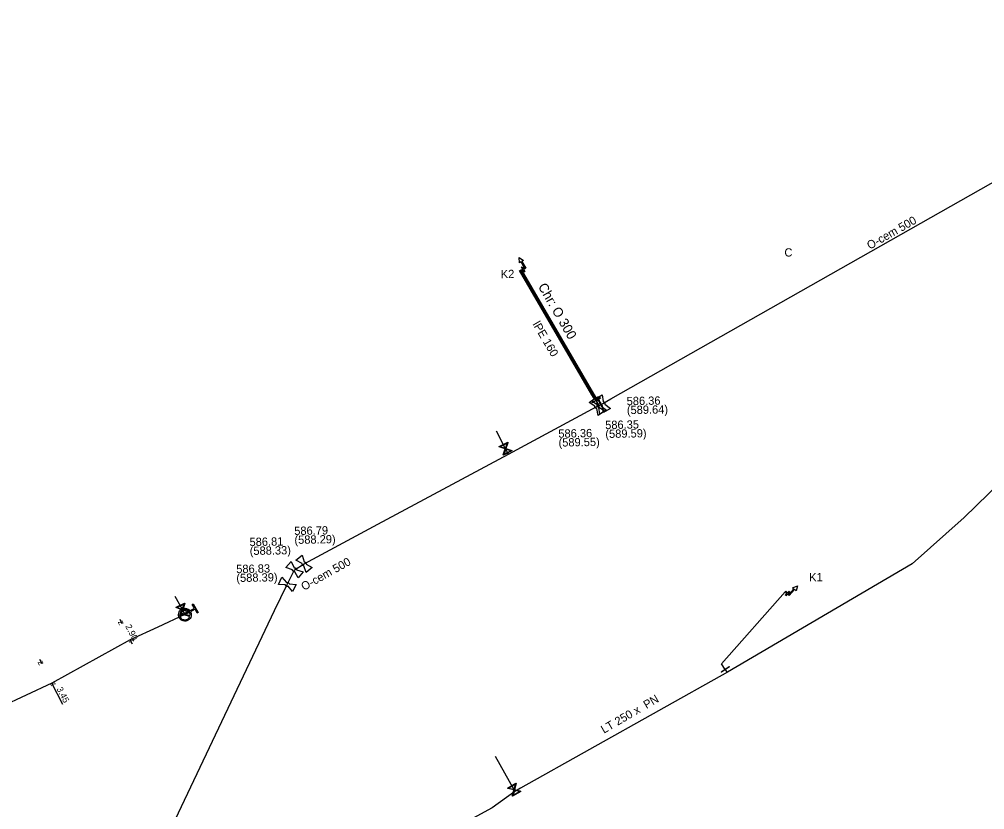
# Model space of a CAD drawing. Extents: x -643544 to -637295, y -1119190 to -1111715.
# Drawn here: x -641216.1 to -641064.3, y -1115318.9 to -1115194.6 of the extents above; entities that cross this region are included whole.
import ezdxf

# ---------------------------------------------------------------- set-up
doc = ezdxf.new("R2010")
doc.units = 0
for name, color, linetype in [('Default', 7, 'Continuous'), ('VP Chránička', 7, 'Continuous'), ('VP Chránička - okraje', 7, 'Continuous'), ('VP Hydrant', 7, 'Continuous'), ('VP Hydrant - popis', 7, 'Continuous'), ('VP Kótování', 7, 'Continuous'), ('VP Lomový bod', 7, 'Continuous'), ('VP Lomový bod - popis', 7, 'Continuous'), ('VP Popis nerozlišený', 7, 'Continuous'), ('VP Přípojka', 7, 'Continuous'), ('VP Řad', 7, 'Continuous'), ('VP Řad - označení', 7, 'Continuous'), ('VP Řad - popis', 7, 'Continuous'), ('VP Šoupě', 7, 'Continuous')]:
    doc.layers.add(name, color=color, linetype=linetype)

msp = doc.modelspace()

# ---------------------------------------------------------------- linework, layer by layer
at = {"layer": 'Default'}
for points in [[(-641125.25, -1115255.21), (-641125.2, -1115255.21), (-641125.15, -1115255.23), (-641125.07, -1115255.27), (-641125.03, -1115255.34), (-641124.98, -1115255.41), (-641124.97, -1115255.49), (-641124.96, -1115255.54), (-641124.98, -1115255.59)], [(-641124.98, -1115255.65), (-641125.03, -1115255.64), (-641125.08, -1115255.61), (-641125.15, -1115255.57), (-641125.2, -1115255.5), (-641125.24, -1115255.43), (-641125.24, -1115255.35), (-641125.24, -1115255.29), (-641125.23, -1115255.24)], [(-641124.88, -1115255.03), (-641124.83, -1115255.04), (-641124.78, -1115255.06), (-641124.71, -1115255.11), (-641124.66, -1115255.18), (-641124.62, -1115255.25), (-641124.62, -1115255.33), (-641124.62, -1115255.39), (-641124.63, -1115255.44)], [(-641124.39, -1115255.35), (-641124.45, -1115255.34), (-641124.49, -1115255.31), (-641124.57, -1115255.27), (-641124.61, -1115255.2), (-641124.65, -1115255.13), (-641124.65, -1115255.04), (-641124.65, -1115254.99), (-641124.64, -1115254.94)], [(-641124.29, -1115254.73), (-641124.23, -1115254.74), (-641124.19, -1115254.77), (-641124.11, -1115254.81), (-641124.07, -1115254.88), (-641124.03, -1115254.95), (-641124.03, -1115255.03), (-641124.03, -1115255.09), (-641124.04, -1115255.14)], [(-641125.31, -1115255.83), (-641125.36, -1115255.83), (-641125.41, -1115255.8), (-641125.49, -1115255.77), (-641125.53, -1115255.7), (-641125.58, -1115255.63), (-641125.59, -1115255.55), (-641125.6, -1115255.5), (-641125.58, -1115255.44)], [(-641172.87, -1115280.85), (-641172.82, -1115280.84), (-641172.77, -1115280.85), (-641172.68, -1115280.87), (-641172.62, -1115280.92), (-641172.56, -1115280.97), (-641172.53, -1115281.05), (-641172.51, -1115281.1), (-641172.51, -1115281.16)], [(-641171.33, -1115280.54), (-641171.38, -1115280.54), (-641171.43, -1115280.52), (-641171.51, -1115280.49), (-641171.56, -1115280.43), (-641171.61, -1115280.36), (-641171.63, -1115280.28), (-641171.64, -1115280.23), (-641171.63, -1115280.17)], [(-641171.31, -1115279.92), (-641171.26, -1115279.92), (-641171.21, -1115279.94), (-641171.13, -1115279.97), (-641171.08, -1115280.03), (-641171.03, -1115280.1), (-641171.01, -1115280.18), (-641171, -1115280.23), (-641171.01, -1115280.28)], [(-641172.77, -1115281.47), (-641172.82, -1115281.48), (-641172.88, -1115281.47), (-641172.96, -1115281.45), (-641173.02, -1115281.4), (-641173.08, -1115281.35), (-641173.11, -1115281.26), (-641173.13, -1115281.21), (-641173.13, -1115281.16)], [(-641173.84, -1115283.75), (-641173.89, -1115283.77), (-641173.94, -1115283.77), (-641174.03, -1115283.78), (-641174.1, -1115283.74), (-641174.17, -1115283.7), (-641174.22, -1115283.63), (-641174.25, -1115283.59), (-641174.26, -1115283.53)], [(-641174.08, -1115283.17), (-641174.03, -1115283.15), (-641173.98, -1115283.15), (-641173.89, -1115283.14), (-641173.82, -1115283.18), (-641173.75, -1115283.22), (-641173.7, -1115283.29), (-641173.67, -1115283.33), (-641173.66, -1115283.38)], [(-641189.16, -1115287.79), (-641189, -1115288.11), (-641189.09, -1115288.47), (-641189.19, -1115288.87), (-641189.55, -1115289.08), (-641189.91, -1115289.29), (-641190.31, -1115289.19), (-641190.71, -1115289.09), (-641190.92, -1115288.73), (-641191.13, -1115288.38), (-641191.03, -1115287.97), (-641190.93, -1115287.57), (-641190.57, -1115287.36), (-641190.22, -1115287.15), (-641189.82, -1115287.25), (-641189.46, -1115287.34), (-641189.25, -1115287.63)], [(-641190.87, -1115288.11), (-641190.9, -1115288.38), (-641190.76, -1115288.63), (-641190.59, -1115288.92), (-641190.26, -1115289), (-641189.93, -1115289.09), (-641189.64, -1115288.91), (-641189.39, -1115288.77), (-641189.3, -1115288.51)], [(-641189.25, -1115288.33), (-641189.21, -1115288.05), (-641189.36, -1115287.8), (-641189.53, -1115287.51), (-641189.86, -1115287.43), (-641190.18, -1115287.35), (-641190.47, -1115287.52), (-641190.73, -1115287.67), (-641190.82, -1115287.93)]]:
    msp.add_open_spline(points, degree=3, dxfattribs=at)
at = {"layer": 'VP Chránička'}
msp.add_lwpolyline([(-641125.6, -1115254.16), (-641125.93, -1115253.59), (-641137.33, -1115234.04)], dxfattribs=at)
at = {"layer": 'VP Chránička - okraje'}
for points in [[(-641137.2, -1115233.96), (-641125.8, -1115253.51), (-641125.47, -1115254.08)], [(-641125.73, -1115254.24), (-641126.06, -1115253.67), (-641137.45, -1115234.11)]]:
    msp.add_lwpolyline(points, dxfattribs=at)
at = {"layer": 'VP Hydrant'}
for points in [[(-641136.85, -1115233.86), (-641136.64, -1115233.74), (-641137.2, -1115232.77), (-641137.47, -1115232.92), (-641137.52, -1115232.09), (-641136.82, -1115232.55), (-641137.09, -1115232.7), (-641136.47, -1115233.78), (-641136.79, -1115233.97), (-641136.6, -1115234.29), (-641136.71, -1115234.36), (-641136.9, -1115234.04), (-641137.22, -1115234.22), (-641137.28, -1115234.11), (-641136.96, -1115233.93), (-641137.15, -1115233.61), (-641137.04, -1115233.54), (-641136.85, -1115233.86)], [(-641095.23, -1115284.87), (-641095.04, -1115285.03), (-641094.3, -1115284.19), (-641094.53, -1115283.99), (-641093.75, -1115283.67), (-641093.97, -1115284.48), (-641094.2, -1115284.27), (-641095.03, -1115285.21), (-641095.31, -1115284.96), (-641095.56, -1115285.24), (-641095.65, -1115285.16), (-641095.4, -1115284.88), (-641095.68, -1115284.63), (-641095.6, -1115284.54), (-641095.32, -1115284.79), (-641095.08, -1115284.51), (-641094.98, -1115284.59), (-641095.23, -1115284.87)], [(-641189.25, -1115287.63), (-641188.55, -1115287.21), (-641188.9, -1115286.62), (-641188.74, -1115286.52), (-641187.94, -1115287.87), (-641188.1, -1115287.96), (-641188.45, -1115287.37), (-641189.16, -1115287.79)], [(-641189.3, -1115288.51), (-641190.87, -1115288.11)], [(-641190.82, -1115287.93), (-641189.25, -1115288.33)]]:
    msp.add_lwpolyline(points, dxfattribs=at)
at = {"layer": 'VP Kótování'}
for points in [[(-641200.3, -1115288.93), (-641199.96, -1115289.6)], [(-641198.31, -1115292.86), (-641198.65, -1115292.19)], [(-641212.9, -1115295.24), (-641212.56, -1115295.91)], [(-641209.26, -1115302.36), (-641210.99, -1115298.98)]]:
    msp.add_lwpolyline(points, dxfattribs=at)
at = {"layer": 'VP Lomový bod'}
for points in [[(-641125.52, -1115254.28), (-641124.44, -1115253.65), (-641124.29, -1115254.73)], [(-641126.51, -1115254.86), (-641125.5, -1115254.14), (-641125.25, -1115255.21)], [(-641125.58, -1115255.44), (-641126.51, -1115254.86)], [(-641126.11, -1115254.6), (-641125.05, -1115253.95), (-641124.88, -1115255.03)], [(-641125.23, -1115255.24), (-641126.11, -1115254.6)], [(-641124.64, -1115254.94), (-641125.52, -1115254.28)], [(-641124.04, -1115255.14), (-641123.16, -1115255.8), (-641124.24, -1115256.43), (-641124.39, -1115255.35)], [(-641124.98, -1115255.59), (-641124.05, -1115256.18), (-641125.06, -1115256.9), (-641125.31, -1115255.83)], [(-641124.63, -1115255.44), (-641123.75, -1115256.08), (-641124.81, -1115256.73), (-641124.98, -1115255.65)], [(-641172.59, -1115279.66), (-641171.63, -1115278.87), (-641171.31, -1115279.92)], [(-641174.18, -1115280.83), (-641173.37, -1115279.88), (-641172.87, -1115280.85)], [(-641173.13, -1115281.16), (-641174.18, -1115280.83)], [(-641171.63, -1115280.17), (-641172.59, -1115279.66)], [(-641171.01, -1115280.28), (-641170.05, -1115280.8), (-641171.01, -1115281.59), (-641171.33, -1115280.54)], [(-641175.36, -1115283.46), (-641174.79, -1115282.34), (-641174.08, -1115283.17)], [(-641172.51, -1115281.16), (-641171.46, -1115281.49), (-641172.27, -1115282.44), (-641172.77, -1115281.47)], [(-641174.26, -1115283.53), (-641175.36, -1115283.46)], [(-641173.66, -1115283.38), (-641172.56, -1115283.46), (-641173.13, -1115284.58), (-641173.84, -1115283.75)]]:
    msp.add_lwpolyline(points, dxfattribs=at)
at = {"layer": 'VP Přípojka'}
for points in [[(-641139.19, -1115262.99), (-641139.65, -1115262.14), (-641141.09, -1115259.38)], [(-641190.06, -1115288.22), (-641190.45, -1115287.43), (-641191.6, -1115285.37)], [(-641138.17, -1115316.02), (-641138.28, -1115315.75), (-641141.24, -1115310.54)]]:
    msp.add_lwpolyline(points, dxfattribs=at)
at = {"layer": 'VP Řad'}
for points in [[(-641195.85, -1115330.09), (-641195.49, -1115329.59), (-641195.08, -1115328.57), (-641192.5, -1115322.48), (-641175.96, -1115287.57), (-641173.96, -1115283.46), (-641172.82, -1115281.16), (-641171.32, -1115280.22), (-641159.71, -1115274.02), (-641139.19, -1115262.99), (-641125.28, -1115255.52), (-641124.93, -1115255.34), (-641124.34, -1115255.04), (-641123.72, -1115254.68), (-641123.1, -1115254.31), (-641017.76, -1115194.64)], [(-641016.54, -1115224.07), (-641018.3, -1115226.08), (-641026.9, -1115234.13), (-641033.61, -1115240.57), (-641043.5, -1115249.75), (-641055.99, -1115261.73), (-641067.56, -1115272.95), (-641075.74, -1115280.21)], [(-641124.93, -1115255.34), (-641125.12, -1115254.99), (-641125.38, -1115254.52), (-641125.6, -1115254.16), (-641137.33, -1115234.04)], [(-641075.74, -1115280.21), (-641104.73, -1115297.24), (-641137.28, -1115315.48)], [(-641104.73, -1115297.24), (-641105.1, -1115296.82), (-641105.69, -1115295.97), (-641095.66, -1115284.61)], [(-641189.5, -1115287.94), (-641190.06, -1115288.22), (-641194.29, -1115290.17), (-641198.65, -1115292.19), (-641210.99, -1115298.98), (-641219.05, -1115302.77), (-641230.92, -1115309.01), (-641237.98, -1115312.1)], [(-641137.28, -1115315.48), (-641138.17, -1115316.02), (-641141.75, -1115318.59), (-641146.55, -1115321.2), (-641152.16, -1115324.37), (-641158.67, -1115328.17), (-641166.16, -1115332), (-641172.65, -1115336.13), (-641178.37, -1115338.96), (-641179.17, -1115339.41), (-641185.86, -1115343.07), (-641190.14, -1115345.63), (-641194.77, -1115348.03), (-641197.45, -1115349.4), (-641197.6, -1115349.47), (-641200.49, -1115351.24), (-641208.35, -1115356.2), (-641210.08, -1115356.84), (-641233.52, -1115370.21)]]:
    msp.add_lwpolyline(points, dxfattribs=at)
at = {"layer": 'VP Šoupě'}
for points in [[(-641124.71, -1115254.18), (-641126.01, -1115254.94), (-641126.05, -1115254.86), (-641124.75, -1115254.1), (-641124.71, -1115254.18)], [(-641138.64, -1115262.48), (-641139.99, -1115263.14), (-641140.02, -1115263.08), (-641139.97, -1115262.96), (-641139.7, -1115262.17), (-641140.62, -1115261.85), (-641140.65, -1115261.79), (-641139.3, -1115261.13), (-641139.27, -1115261.19), (-641139.59, -1115262.11), (-641138.8, -1115262.38), (-641138.67, -1115262.42), (-641138.64, -1115262.48)], [(-641140.47, -1115261.81), (-641139.67, -1115262.08), (-641139.4, -1115261.29), (-641140.47, -1115261.81)], [(-641138.83, -1115262.47), (-641139.62, -1115262.19), (-641139.89, -1115262.99), (-641138.83, -1115262.47)], [(-641189.45, -1115287.79), (-641190.81, -1115288.42), (-641190.84, -1115288.36), (-641190.79, -1115288.24), (-641190.51, -1115287.45), (-641191.42, -1115287.12), (-641191.45, -1115287.06), (-641190.09, -1115286.43), (-641190.06, -1115286.49), (-641190.39, -1115287.4), (-641189.6, -1115287.69), (-641189.48, -1115287.73), (-641189.45, -1115287.79)], [(-641191.27, -1115287.08), (-641190.48, -1115287.37), (-641190.19, -1115286.58), (-641191.27, -1115287.08)], [(-641189.63, -1115287.77), (-641190.42, -1115287.48), (-641190.71, -1115288.27), (-641189.63, -1115287.77)], [(-641104.45, -1115296.44), (-641105.7, -1115297.27), (-641105.75, -1115297.2), (-641104.5, -1115296.36), (-641104.45, -1115296.44)], [(-641137.26, -1115316.02), (-641138.55, -1115316.77), (-641138.59, -1115316.71), (-641138.55, -1115316.59), (-641138.33, -1115315.78), (-641139.27, -1115315.53), (-641139.31, -1115315.47), (-641138.01, -1115314.72), (-641137.98, -1115314.78), (-641138.23, -1115315.72), (-641137.41, -1115315.93), (-641137.29, -1115315.96), (-641137.26, -1115316.02)], [(-641139.13, -1115315.48), (-641138.31, -1115315.69), (-641138.1, -1115314.88), (-641139.13, -1115315.48)], [(-641137.44, -1115316.01), (-641138.25, -1115315.8), (-641138.46, -1115316.61), (-641137.44, -1115316.01)]]:
    msp.add_lwpolyline(points, dxfattribs=at)

# ---------------------------------------------------------------- texts
at = {"layer": 'VP Hydrant - popis'}
for s, p in [('K2', (-641140.38, -1115235.34)), ('K1', (-641091.9, -1115283))]:
    msp.add_text(s, height=1.3, rotation=1, dxfattribs=at).set_placement(p)
at = {"layer": 'VP Kótování'}
for s, rotation, p in [('z', 296.8566, (-641200.63, -1115289.38)), ('2.90', 296.8566, (-641199.45, -1115290.05)), ('z', 116.8566, (-641197.98, -1115292.41)), ('z', 297.0701, (-641213.23, -1115295.69)), ('z', 117.0701, (-641210.32, -1115299.2)), ('3.45', 297.0701, (-641210.25, -1115299.88))]:
    msp.add_text(s, height=1, rotation=rotation, dxfattribs=at).set_placement(p)
at = {"layer": 'VP Lomový bod - popis'}
for s, p in [('586.36', (-641120.59, -1115255.3)), ('(589.64)', (-641120.56, -1115256.7)), ('586.35', (-641123.97, -1115259.05)), ('586.36', (-641131.33, -1115260.41)), ('(589.59)', (-641123.94, -1115260.45)), ('(589.55)', (-641131.3, -1115261.81)), ('586.79', (-641172.85, -1115275.7)), ('586.81', (-641179.88, -1115277.44)), ('(588.29)', (-641172.82, -1115277.1)), ('(588.33)', (-641179.85, -1115278.84)), ('586.83', (-641181.97, -1115281.69)), ('(588.39)', (-641181.95, -1115283.09))]:
    msp.add_text(s, height=1.3, rotation=1, dxfattribs=at).set_placement(p)
at = {"layer": 'VP Popis nerozlišený'}
msp.add_text('Chr: O 300', height=1.5, rotation=300.0757, dxfattribs=at).set_placement((-641134.59, -1115236.62))
at = {"layer": 'VP Řad - označení'}
msp.add_text('C', height=1.3, dxfattribs=at).set_placement((-641095.8, -1115231.93))
at = {"layer": 'VP Řad - popis'}
for s, rotation, p in [('O-cem 500', 29.5309, (-641082.38, -1115230.86)), ('lPE 160', 300.2304, (-641135.44, -1115242.56)), ('O-cem 500', 29.2835, (-641171.33, -1115284.49)), ('LT 250 x  PN ', 30.1687, (-641124.18, -1115306.95))]:
    msp.add_text(s, height=1.3, rotation=rotation, dxfattribs=at).set_placement(p)

doc.saveas('drawing.dxf')
